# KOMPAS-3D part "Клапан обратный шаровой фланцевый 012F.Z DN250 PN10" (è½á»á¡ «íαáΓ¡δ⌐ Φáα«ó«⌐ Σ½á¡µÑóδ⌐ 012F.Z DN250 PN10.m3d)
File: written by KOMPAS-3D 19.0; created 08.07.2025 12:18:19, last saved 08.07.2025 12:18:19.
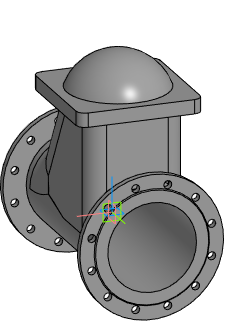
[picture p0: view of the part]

Document properties: Полное имя файла: E:\Dendor Работа Сачек\3D для проектировщиков\5.3 Тип 012F, 012F.Z Клапан обратный шаровой фланцевый\stp_Клапан обратный шаровой фланцевый 012F.Z PN10_16\Клапан обратный шаровой фланцевый 012F.Z DN250 PN10.m3d

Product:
- Part/product: Клапан обратный шаровой фланцевый 012F.Z DN250 PN10

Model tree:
1. Операция без истории:1  (labels: Клапан обратный шаровой фланцевый 012F.Z DN250 PN10)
